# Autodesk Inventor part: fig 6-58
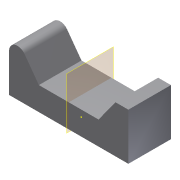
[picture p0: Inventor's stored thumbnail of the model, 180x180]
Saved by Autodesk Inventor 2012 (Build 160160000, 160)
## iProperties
Created: 2011-07
Part Number: fig 6-58
Material: Default
Document SubType Name: Modeling
Designer: CadCim
Density: 1 g/cm^3
Author: CadCim
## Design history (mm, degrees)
sketch "Sketch1"
  geometry: 1 further point
sketch "Sketch2"
  geometry: L1 (3, -4)-(17, -4); L2 (17, -4)-(17, 7); L3 (17, 7)-(14, 7); L4 (14, 7)-(10, 1.5); L5 (10, 1.5)-(3, 1.5); L6 (3, -4)-(-11, -4); L7 (-11, -4)-(-11, 7); L8 (-11, 7)-(-8, 7); L9 (-8, 7)-(-4, 1.5); L10 (-4, 1.5)-(3, 1.5); 1 further point
  constraints: 20 end point, 2 parallel, 1 perpendicular
extrude "Extrusion1" new body sketch "Sketch2" distance "d0" = 10; taper "d1" = 0 deg
fillet "Fillet1" dims "d2" = 2
workplane "Work Plane1"
body "Solid1"
